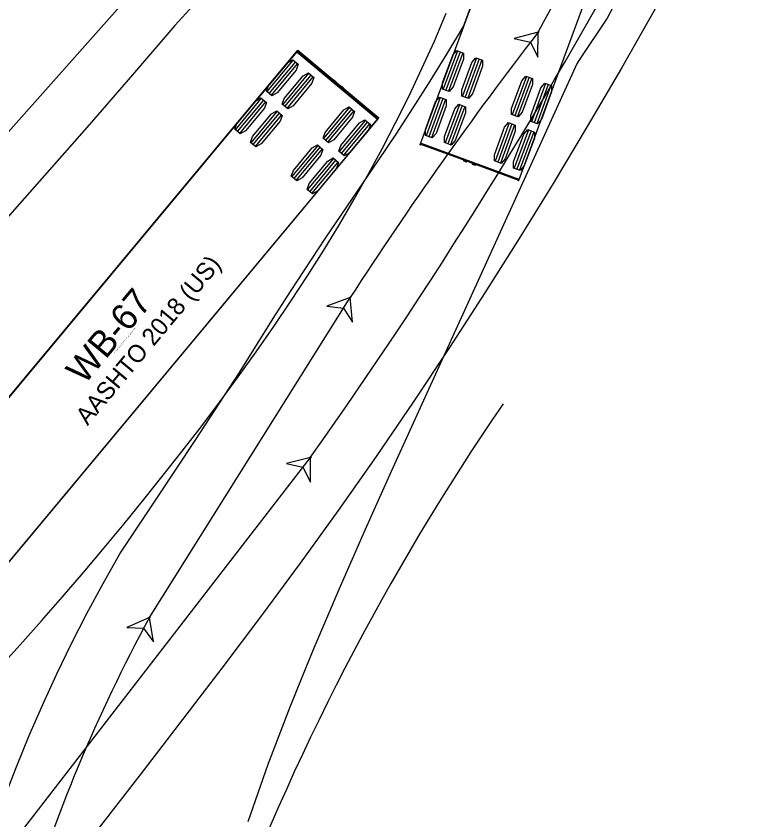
# Model space of a CAD drawing. Extents: x 973688 to 979179, y 703586 to 707602.
# Drawn here: x 976668.5 to 976727.4, y 705601.3 to 705666.2 of the extents above; entities that cross this region are included whole.
import ezdxf

# ---------------------------------------------------------------- set-up
doc = ezdxf.new("R2010")
doc.units = 0
for name, color, linetype in [('EB Left', 7, 'Continuous'), ('R_Prop EP', 7, 'Continuous'), ('SB Left', 7, 'Continuous'), ('SB Right', 7, 'Continuous')]:
    doc.layers.add(name, color=color, linetype=linetype)

msp = doc.modelspace()

# ---------------------------------------------------------------- linework, layer by layer
at = {"layer": 'EB Left'}
msp.add_line((976636.105, 705557.917), (976692.267, 705630.593), dxfattribs=at)
for points in [[(976667.091, 705613.536), (976668.83, 705615.453), (976670.552, 705617.388), (976672.258, 705619.34), (976673.948, 705621.309), (976675.617, 705623.289), (976677.23, 705625.236), (976678.819, 705627.187), (976680.385, 705629.142), (976681.923, 705631.097), (976683.431, 705633.054), (976684.947, 705635.065), (976686.432, 705637.082), (976687.884, 705639.109), (976689.301, 705641.145), (976690.684, 705643.192), (976692.029, 705645.249), (976693.336, 705647.317), (976694.594, 705649.382), (976695.792, 705651.422), (976696.952, 705653.477), (976698.074, 705655.549), (976699.16, 705657.642), (976700.219, 705659.776), (976701.258, 705661.971), (976702.259, 705664.192), (976703.224, 705666.439)], [(976720.066, 705666.787), (976717.348, 705661.995), (976714.598, 705657.289), (976711.84, 705652.687), (976709.106, 705648.242), (976706.336, 705643.859), (976703.488, 705639.466), (976700.549, 705635.052), (976697.551, 705630.665), (976694.495, 705626.307), (976691.435, 705622.052), (976688.318, 705617.825), (976685.116, 705613.589), (976678.486, 705604.943), (976671.776, 705596.27)], [(976692.267, 705630.593), (976690.334, 705630.082), (976691.656, 705629.802), (976692.261, 705628.593), (976692.267, 705630.593)]]:
    msp.add_lwpolyline(points, dxfattribs=at)
msp.add_lwpolyline([(976692.267, 705630.593), (976690.334, 705630.082), (976691.656, 705629.802), (976692.261, 705628.593)], close=True, dxfattribs=at)
msp.add_circle((976692.267, 705630.593), 0.0417, dxfattribs=at)
msp.add_arc((976347.09, 705875.165), 423.04, 324.68102, 332.17475, dxfattribs=at)
at = {"layer": 'R_Prop EP'}
msp.add_arc((976872.704, 705521.726), 200, 145.53427, 159.7843, dxfattribs=at)
at = {"layer": 'SB Left'}
for p, q in [((976691.151, 705663.335), (976697.683, 705657.896)), ((976688.762, 705660.108), (976690.874, 705662.644)), ((976688.938, 705659.961), (976691.05, 705662.497)), ((976689.114, 705659.815), (976691.226, 705662.35)), ((976690.03, 705659.052), (976692.142, 705661.588)), ((976690.206, 705658.905), (976692.318, 705661.441)), ((976690.382, 705658.759), (976692.494, 705661.295)), ((976694.054, 705661.01), (976694.258, 705660.84)), ((976694.462, 705660.67), (976694.417, 705660.615)), ((976694.666, 705660.5), (976694.87, 705660.33)), ((976686.202, 705657.034), (976688.314, 705659.57)), ((976686.378, 705656.888), (976688.49, 705659.423)), ((976686.554, 705656.741), (976688.666, 705659.277)), ((976687.47, 705655.978), (976689.582, 705658.514)), ((976693.321, 705656.311), (976695.433, 705658.847)), ((976693.497, 705656.164), (976695.609, 705658.7)), ((976693.673, 705656.018), (976695.785, 705658.553)), ((976687.646, 705655.832), (976689.758, 705658.367)), ((976687.822, 705655.685), (976689.934, 705658.221)), ((976694.589, 705655.255), (976696.701, 705657.791)), ((976694.765, 705655.108), (976696.877, 705657.644)), ((976694.941, 705654.962), (976697.053, 705657.498)), ((976690.761, 705653.237), (976692.873, 705655.773)), ((976690.938, 705653.091), (976693.049, 705655.626)), ((976691.114, 705652.944), (976693.225, 705655.48)), ((976692.029, 705652.181), (976694.141, 705654.717)), ((976692.205, 705652.035), (976694.317, 705654.57)), ((976692.382, 705651.888), (976694.493, 705654.424))]:
    msp.add_line(p, q, dxfattribs=at)
for points in [[(976588.055, 705537.745), (976588.824, 705539.157), (976589.654, 705540.534), (976590.538, 705541.871), (976591.471, 705543.167), (976592.449, 705544.42), (976598.86, 705552.142), (976600.338, 705554.112), (976601.805, 705555.982), (976603.255, 705557.773), (976691.242, 705663.444), (976697.773, 705658.004), (976697.689, 705657.903), (976697.689, 705657.903)], [(976691.214, 705663.375), (976691.197, 705663.389), (976691.152, 705663.335), (976687.525, 705658.98), (976657.325, 705622.717), (976660.59, 705619.997), (976663.856, 705617.278), (976694.056, 705653.541), (976697.682, 705657.896), (976697.727, 705657.95), (976697.711, 705657.964)], [(976694.305, 705660.892), (976694.1, 705661.063), (976694.099, 705661.063), (976694.054, 705661.01), (976694.026, 705661.032), (976691.233, 705663.359), (976691.232, 705663.36)], [(976694.661, 705660.504), (976694.261, 705660.838)], [(976697.692, 705657.98), (976697.692, 705657.98), (976694.898, 705660.307), (976694.871, 705660.33), (976694.915, 705660.383), (976694.915, 705660.385), (976694.709, 705660.555)], [(976697.689, 705657.903), (976637.3, 705585.378)]]:
    msp.add_lwpolyline(points, dxfattribs=at)
for points in [[(976689.158, 705659.778), (976688.718, 705660.144), (976688.881, 705660.61), (976690.402, 705662.435), (976690.83, 705662.68), (976691.27, 705662.314), (976691.106, 705661.849), (976689.586, 705660.023)], [(976690.426, 705658.722), (976689.986, 705659.088), (976690.149, 705659.554), (976691.67, 705661.379), (976692.098, 705661.624), (976692.537, 705661.258), (976692.374, 705660.793), (976690.854, 705658.967)], [(976686.598, 705656.705), (976686.158, 705657.071), (976686.322, 705657.536), (976687.842, 705659.362), (976688.27, 705659.606), (976688.71, 705659.24), (976688.547, 705658.775), (976687.026, 705656.949)], [(976687.866, 705655.649), (976687.426, 705656.015), (976687.59, 705656.48), (976689.11, 705658.306), (976689.538, 705658.55), (976689.978, 705658.184), (976689.814, 705657.719), (976688.294, 705655.893)], [(976693.717, 705655.981), (976693.278, 705656.347), (976693.441, 705656.813), (976694.961, 705658.638), (976695.389, 705658.883), (976695.829, 705658.517), (976695.666, 705658.052), (976694.145, 705656.226)], [(976694.985, 705654.925), (976694.545, 705655.291), (976694.709, 705655.757), (976696.229, 705657.582), (976696.657, 705657.827), (976697.097, 705657.461), (976696.934, 705656.996), (976695.413, 705655.17)], [(976691.157, 705652.908), (976690.718, 705653.274), (976690.881, 705653.739), (976692.402, 705655.565), (976692.83, 705655.809), (976693.269, 705655.443), (976693.106, 705654.978), (976691.585, 705653.152)], [(976692.425, 705651.852), (976691.986, 705652.218), (976692.149, 705652.683), (976693.669, 705654.509), (976694.097, 705654.754), (976694.537, 705654.387), (976694.374, 705653.922), (976692.853, 705652.096)]]:
    msp.add_lwpolyline(points, close=True, dxfattribs=at)
for centre in [(976691.245, 705663.394), (976697.724, 705657.998)]:
    msp.add_circle(centre, 0.0266, dxfattribs=at)
for centre, radius, start, end in [((976692.507, 705664.929), 2.022, 230.21257, 230.89633), ((976694.282, 705660.865), 0.0354, 54.5041, 226.68957), ((976694.283, 705660.865), 0.0352, 231.18689, 50.1873), ((976694.687, 705660.528), 0.0352, 50.23783, 229.23824), ((976694.687, 705660.528), 0.0353, 233.54875, 51.8984), ((976697.724, 705657.998), 0.0363, 249.29001, 210.45136)]:
    msp.add_arc(centre, radius, start, end, dxfattribs=at)
at = {"layer": 'SB Right'}
for p, q in [((976685.668, 705676.879), (976635.767, 705620.712)), ((976704.119, 705663.397), (976702.977, 705660.301)), ((976704.334, 705663.317), (976703.192, 705660.221)), ((976704.549, 705663.238), (976703.407, 705660.142)), ((976705.667, 705662.826), (976704.525, 705659.73)), ((976705.882, 705662.747), (976704.74, 705659.65)), ((976706.097, 705662.667), (976704.955, 705659.571)), ((976709.686, 705661.344), (976708.544, 705658.248)), ((976709.901, 705661.265), (976708.759, 705658.168)), ((976710.116, 705661.185), (976708.974, 705658.089)), ((976711.234, 705660.773), (976710.092, 705657.677)), ((976711.449, 705660.694), (976710.307, 705657.597)), ((976711.664, 705660.614), (976710.522, 705657.518)), ((976702.735, 705659.644), (976701.593, 705656.548)), ((976702.95, 705659.565), (976701.808, 705656.468)), ((976703.165, 705659.485), (976702.023, 705656.389)), ((976704.283, 705659.073), (976703.141, 705655.977)), ((976704.498, 705658.994), (976703.356, 705655.897)), ((976704.713, 705658.914), (976703.571, 705655.818)), ((976708.302, 705657.591), (976707.16, 705654.495)), ((976708.517, 705657.512), (976707.375, 705654.415)), ((976708.732, 705657.432), (976707.59, 705654.336)), ((976709.85, 705657.02), (976708.708, 705653.924)), ((976710.065, 705656.941), (976708.923, 705653.845)), ((976710.28, 705656.861), (976709.138, 705653.765)), ((976709.108, 705653.021), (976701.133, 705655.962)), ((976704.847, 705654.517), (976704.597, 705654.609)), ((976705.096, 705654.425), (976705.12, 705654.491)), ((976705.594, 705654.241), (976705.345, 705654.333)), ((976679.278, 705617.67), (976695.466, 705643.49))]:
    msp.add_line(p, q, dxfattribs=at)
for points in [[(976709.062, 705652.962), (976709.083, 705652.955), (976709.107, 705653.021), (976711.069, 705658.338), (976727.397, 705702.615), (976723.409, 705704.085), (976719.422, 705705.556), (976703.094, 705661.279), (976701.133, 705655.962), (976701.109, 705655.895), (976701.129, 705655.888)], [(976667.552, 705603.063), (976668.543, 705605.625), (976669.58, 705608.148), (976670.666, 705610.646), (976671.801, 705613.115), (976672.984, 705615.555), (976674.219, 705617.976), (976675.525, 705620.41), (976676.879, 705622.809), (976679.952, 705627.409), (976682.954, 705631.952), (976686.537, 705637.449), (976689.249, 705641.796), (976690.639, 705643.968), (976693.467, 705648.275), (976697.782, 705654.609), (976699.17, 705656.684), (976700.544, 705658.791), (976701.909, 705660.942), (976703.264, 705663.138), (976704.605, 705665.378), (976719.091, 705704.657)], [(976717.451, 705668.407), (976716.214, 705666.033), (976713.919, 705662.633), (976713.748, 705662.351), (976698.787, 705629.451), (976696.687, 705624.779), (976694.577, 705619.982), (976692.541, 705615.197), (976691.558, 705612.811), (976690.604, 705610.427), (976689.703, 705608.108), (976688.836, 705605.795), (976688.005, 705603.485), (976687.212, 705601.175)], [(976683.104, 705667.39), (976681.323, 705665.437), (976677.908, 705661.464), (976674.411, 705657.442), (976667.396, 705649.471)], [(976710.624, 705664.9), (976708.69, 705664.387), (976710.013, 705664.108), (976710.618, 705662.9), (976710.624, 705664.9)], [(976701.152, 705655.879), (976701.153, 705655.879), (976704.564, 705654.621), (976704.597, 705654.609), (976704.573, 705654.543), (976704.574, 705654.542), (976704.825, 705654.45)], [(976704.853, 705654.515), (976705.342, 705654.334)], [(976705.318, 705654.268), (976705.569, 705654.176), (976705.57, 705654.176), (976705.594, 705654.241), (976705.628, 705654.229), (976709.039, 705652.971), (976709.04, 705652.971)], [(976695.466, 705643.49), (976693.591, 705642.792), (976694.935, 705642.642), (976695.654, 705641.499), (976695.466, 705643.49)], [(976679.278, 705617.67), (976677.45, 705616.858), (976678.8, 705616.792), (976679.589, 705615.694), (976679.278, 705617.67)]]:
    msp.add_lwpolyline(points, dxfattribs=at)
for points in [[(976710.624, 705664.9), (976708.69, 705664.387), (976710.013, 705664.108), (976710.618, 705662.9)], [(976704.066, 705663.416), (976704.602, 705663.219), (976704.604, 705662.725), (976703.782, 705660.496), (976703.46, 705660.122), (976702.924, 705660.32), (976702.922, 705660.813), (976703.744, 705663.043)], [(976705.614, 705662.846), (976706.15, 705662.648), (976706.152, 705662.155), (976705.33, 705659.925), (976705.008, 705659.551), (976704.472, 705659.749), (976704.47, 705660.242), (976705.292, 705662.472)], [(976709.632, 705661.363), (976710.169, 705661.166), (976710.171, 705660.672), (976709.349, 705658.443), (976709.027, 705658.069), (976708.491, 705658.267), (976708.489, 705658.76), (976709.311, 705660.99)], [(976711.18, 705660.793), (976711.717, 705660.595), (976711.719, 705660.102), (976710.897, 705657.872), (976710.575, 705657.498), (976710.039, 705657.696), (976710.037, 705658.189), (976710.859, 705660.419)], [(976702.682, 705659.663), (976703.218, 705659.466), (976703.22, 705658.972), (976702.398, 705656.743), (976702.076, 705656.369), (976701.54, 705656.567), (976701.538, 705657.06), (976702.36, 705659.29)], [(976704.23, 705659.093), (976704.766, 705658.895), (976704.768, 705658.402), (976703.946, 705656.172), (976703.624, 705655.798), (976703.088, 705655.996), (976703.086, 705656.489), (976703.908, 705658.719)], [(976708.248, 705657.611), (976708.785, 705657.413), (976708.787, 705656.92), (976707.965, 705654.69), (976707.643, 705654.316), (976707.107, 705654.514), (976707.105, 705655.007), (976707.927, 705657.237)], [(976709.796, 705657.04), (976710.333, 705656.842), (976710.335, 705656.349), (976709.513, 705654.119), (976709.191, 705653.746), (976708.655, 705653.943), (976708.653, 705654.437), (976709.475, 705656.666)], [(976695.466, 705643.49), (976693.591, 705642.792), (976694.935, 705642.642), (976695.654, 705641.499)], [(976679.278, 705617.67), (976677.45, 705616.858), (976678.8, 705616.792), (976679.589, 705615.694)]]:
    msp.add_lwpolyline(points, close=True, dxfattribs=at)
for centre, radius in [((976710.624, 705664.9), 0.0417), ((976710.624, 705664.9), 0.0417), ((976701.129, 705655.852), 0.0266), ((976709.039, 705652.934), 0.0266), ((976695.466, 705643.49), 0.0417), ((976695.466, 705643.49), 0.0417), ((976679.278, 705617.67), 0.0417), ((976679.278, 705617.67), 0.0417)]:
    msp.add_circle(centre, radius, dxfattribs=at)
for centre, radius, start, end in [((976525.035, 705767.141), 211.887, 331.14948, 339.07382), ((976963.94, 705469.487), 319.93, 142.35279, 147.05206), ((976701.129, 705655.852), 0.0363, 88.8345, 49.99585), ((976704.836, 705654.483), 0.0353, 73.09323, 251.44288), ((976704.837, 705654.483), 0.0352, 249.78232, 68.78273), ((976705.33, 705654.301), 0.0352, 70.73137, 249.73178), ((976705.331, 705654.301), 0.0354, 254.04859, 66.23405), ((976708.363, 705651.065), 2.022, 69.75705, 70.44081), ((976791.709, 705556.495), 127.997, 151.44886, 163.38953)]:
    msp.add_arc(centre, radius, start, end, dxfattribs=at)

# ---------------------------------------------------------------- texts
at = {"layer": 'SB Left'}
for s, height, p in [('AASHTO 2018 (US)', 1.41667, (976674.282, 705633.106)), ('WB-67', 2.125, (976674.019, 705636.387)), ('(c) 2020 Transoft Solutions, Inc. All rights reserved.', 0.085, (976676.468, 705638.996))]:
    msp.add_text(s, height=height, rotation=50.21257, dxfattribs=at).set_placement(p)

doc.saveas('drawing.dxf')
